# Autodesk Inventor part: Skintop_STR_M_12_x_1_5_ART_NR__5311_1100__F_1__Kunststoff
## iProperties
Created: 2005-01
Part Number: Skintop_STR_M_12_x_1_5_ART_NR__5311_1100__F_1__Kunststoff
Material: kunststoff
Description: STR-M - Kabelverschraubung Kunststoff
Vendor: LAPP
Document SubType Name: Modeling
Designer: DB
Manufacturer: Standard
Standards Organization: Custom
CNS_NB: Skintop STR-M 12 x 1.5-ART.NR. 5311 1100-(F=1)
CNS_NN: STR-M
CNS_NT: Kabelverschraubung Kunststoff
CNS_NBSYN: Skintop STR-$GEW.-ART.NR. $ATN.-(F=$F.)
CNS_LINA: Skintop STR-M 12 x 1.5-ART.NR. 5311 1100-(F=1)
CNS_ATN: 5311 1100
CNS_GEW: M 12 x 1.5
CNS_FMIN: 1.0
CNS_FMAX: 5.0
CNS_F: 1
CNS_NDM: 12.0
CNS_P: 1.5
CNS_X: 3.800
CNS_SW: 15
CNS_A: 16.6
CNS_C: 30.0
CNS_D: 8.0
CNS_E: 13.0
CNS_H: 8.9
CNS_J: 3.3
CNS_K: 5.2
CNS_L: 13.2
CNS_RAL7001: X
CNS_XMAX: 3.800
CNS_MATERIAL: Kunststoff
CNS_KT: DUMMY
CNS_DENSITY: 0.000000
CNS_DENSITYUNITBASE: 0.000000
CNS_LINA2: Skintop STR-M 12 x 1.5-ART.NR. 5311 1100-(F=1)
PSOL_IDENT_0: {I:\Cadenas Partsolutions\data\23d-libs\lapp_kabel\skintop_metrisch\str_m.prj},162 {VTYP=3D},{NB=Ski
PSOL_IDENT_1: ntop STR-M 12 x 1.5-ART.NR. 5311 1100-(F=1)},{NN=STR-M},{DATE=2.4.2003},{GEOMDATE=22.11.2002},{VERSI
PSOL_IDENT_2: ON=v1},{LINEID=10},{LINESUBID=-1},{WBVAR=F}  {NB=Skintop STR-M 12 x 1.5-ART.NR. 5311 1100-(F=1)},{LI
PSOL_IDENT_3: NA=Skintop STR-M 12 x 1.5-ART.NR. 5311 1100-(F=1)},{KT=DUMMY},{IDNR=},{ATN=5311 1100},{GEW=M 12 x 1.
PSOL_IDENT_4: 5},{FMIN=1.0},{FMAX=5.0},{F=1},{NDM=12.0},{P=1.5},{X=3.8},{SW=15},{A=16.6},{C=30.0},{D=8.0},{E=13.0}
PSOL_IDENT_5: ,{H=8.9},{J=3.3},{K=5.2},{L=13.2},{RAL7001=X},{RAL7035=},{RAL9005=},{XMAX=3.8},{MATERIAL=Kunststoff}
Title: Skintop STR-M 12 x 1.5-ART.NR. 5311 1100-(F=1)
Author: DB
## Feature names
1. Drehung1 [Revolution]
2. Extrusion1
3. Extrusion2
4. Extrusion3
